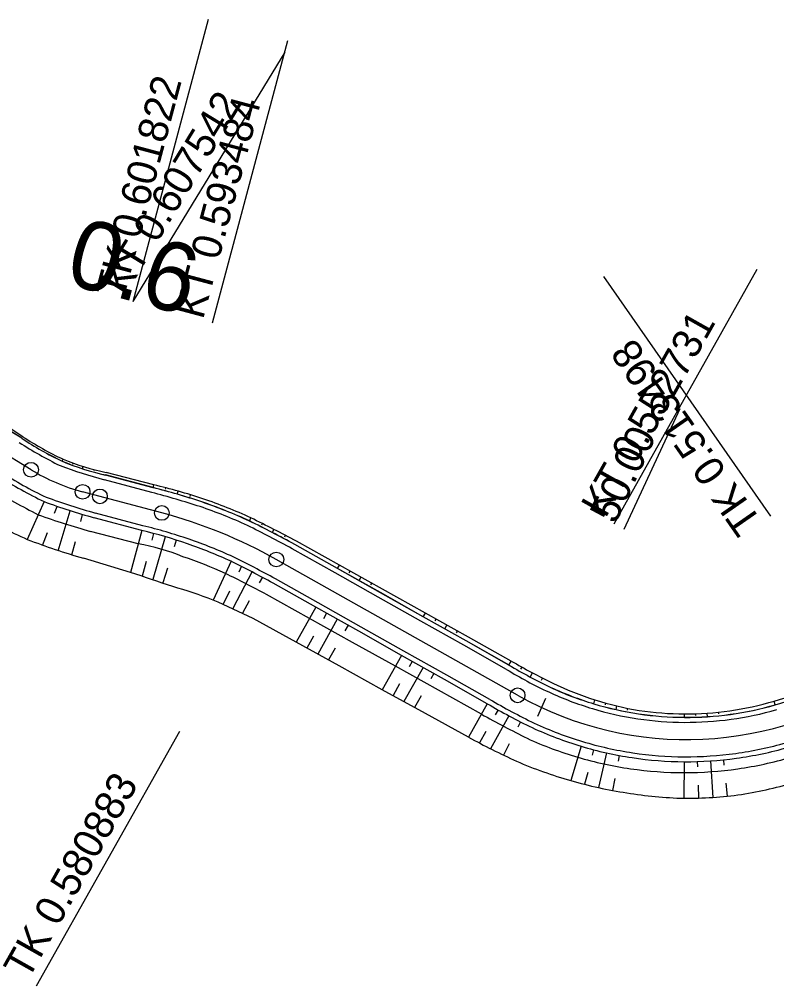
# Model space of a CAD drawing. Extents: x -481645 to -478728, y -1113199 to -1110710.
# Drawn here: x -479750.6 to -479673.5, y -1112836.4 to -1112738.2 of the extents above; entities that cross this region are included whole.
import ezdxf

# ---------------------------------------------------------------- set-up
doc = ezdxf.new("R2010")
doc.units = 0
for name, color, linetype in [('CP14_HRANA_TELESO', 7, 'Continuous'), ('CP14_OSA', 7, 'Continuous'), ('CP14_PRIKOP', 7, 'Continuous'), ('CP1_HATCH_SLOPE_L', 7, 'Continuous'), ('CP1_HATCH_SLOPE_R', 7, 'Continuous'), ('CP1_HLBODY', 7, 'Continuous'), ('CP1_HRANA_TELESO', 7, 'Continuous'), ('CP1_OSA', 7, 'Continuous'), ('CP1_STANICENI', 7, 'Continuous'), ('CP1_VOZOVKA', 7, 'Continuous'), ('CP1_ZPEVKRAJ', 7, 'Continuous')]:
    doc.layers.add(name, color=color, linetype=linetype)

msp = doc.modelspace()

# ---------------------------------------------------------------- linework, layer by layer
at = {"layer": 'CP14_HRANA_TELESO'}
for p, q in [((-479748.026, -1112787.238), (-479749.742, -1112791.086)), ((-479746.739, -1112787.764), (-479746.992, -1112788.444)), ((-479745.422, -1112788.209), (-479746.651, -1112792.264)), ((-479744.144, -1112788.563), (-479744.329, -1112789.258)), ((-479747.73, -1112790.424), (-479748.215, -1112791.723)), ((-479738.105, -1112790.173), (-479739.241, -1112794.437)), ((-479736.897, -1112790.494), (-479737.078, -1112791.172)), ((-479735.734, -1112790.814), (-479736.98, -1112795.144)), ((-479744.876, -1112791.312), (-479745.238, -1112792.669)), ((-479734.591, -1112791.158), (-479734.8, -1112791.822)), ((-479737.651, -1112793.328), (-479738.045, -1112794.804)), ((-479729.025, -1112793.302), (-479730.835, -1112797.248)), ((-479727.946, -1112793.813), (-479728.244, -1112794.423)), ((-479735.484, -1112793.994), (-479735.959, -1112795.501)), ((-479726.881, -1112794.351), (-479728.836, -1112798.106)), ((-479725.829, -1112794.916), (-479726.154, -1112795.505)), ((-479729.187, -1112796.348), (-479729.831, -1112797.664)), ((-479727.166, -1112797.334), (-479727.852, -1112798.574)), ((-479720.396, -1112797.971), (-479722.397, -1112801.528)), ((-479719.306, -1112798.584), (-479719.628, -1112799.156)), ((-479718.217, -1112799.197), (-479720.207, -1112802.735)), ((-479717.127, -1112799.81), (-479717.446, -1112800.376)), ((-479720.626, -1112800.929), (-479721.302, -1112802.131)), ((-479718.438, -1112802.14), (-479719.112, -1112803.338)), ((-479711.68, -1112802.875), (-479713.638, -1112806.354)), ((-479710.591, -1112803.488), (-479710.901, -1112804.039)), ((-479709.501, -1112804.1), (-479711.448, -1112807.56)), ((-479708.412, -1112804.713), (-479708.719, -1112805.259)), ((-479711.877, -1112805.774), (-479712.543, -1112806.957)), ((-479709.69, -1112806.984), (-479710.353, -1112808.163)), ((-479702.965, -1112807.778), (-479704.877, -1112811.178)), ((-479701.875, -1112808.391), (-479702.174, -1112808.921)), ((-479700.773, -1112809.01), (-479702.628, -1112812.36)), ((-479699.598, -1112809.634), (-479699.87, -1112810.17)), ((-479703.121, -1112810.605), (-479703.77, -1112811.759)), ((-479700.729, -1112811.86), (-479701.316, -1112813.015)), ((-479693.431, -1112812.103), (-479694.475, -1112815.584)), ((-479692.15, -1112812.463), (-479692.297, -1112813.023)), ((-479690.857, -1112812.777), (-479691.648, -1112816.311)), ((-479689.554, -1112813.044), (-479689.659, -1112813.606)), ((-479678.956, -1112813.485), (-479678.902, -1112814.024)), ((-479682.941, -1112813.675), (-479682.963, -1112817.393)), ((-479681.611, -1112813.659), (-479681.594, -1112814.208)), ((-479680.282, -1112813.595), (-479680.038, -1112817.304)), ((-479692.756, -1112814.778), (-479693.068, -1112815.972)), ((-479689.99, -1112815.383), (-479690.217, -1112816.598)), ((-479681.539, -1112816.066), (-479681.5, -1112817.375)), ((-479678.714, -1112815.873), (-479678.581, -1112817.182))]:
    msp.add_line(p, q, dxfattribs=at)
at = {"layer": 'CP14_OSA'}
msp.add_circle((-479742.357, -1112786.711), 0.75, dxfattribs=at)
at = {"layer": 'CP14_PRIKOP'}
for p, q in [((-479746.194, -1112783.128), (-479746.106, -1112782.931)), ((-479745.167, -1112783.548), (-479745.166, -1112783.544)), ((-479745.126, -1112783.437), (-479745.088, -1112783.335)), ((-479744.116, -1112783.903), (-479744.047, -1112783.674)), ((-479742.951, -1112784.089), (-479742.92, -1112783.973)), ((-479742.985, -1112784.215), (-479742.983, -1112784.21)), ((-479736.946, -1112785.824), (-479736.868, -1112785.532)), ((-479735.696, -1112785.99), (-479735.658, -1112785.844)), ((-479735.738, -1112786.146), (-479735.736, -1112786.142)), ((-479734.49, -1112786.489), (-479734.401, -1112786.18)), ((-479733.239, -1112786.866), (-479733.237, -1112786.862)), ((-479733.188, -1112786.704), (-479733.14, -1112786.55)), ((-479727.148, -1112789.212), (-479727.002, -1112788.893)), ((-479725.968, -1112789.771), (-479725.966, -1112789.766)), ((-479725.887, -1112789.606), (-479725.811, -1112789.45)), ((-479724.802, -1112790.36), (-479724.634, -1112790.038)), ((-479723.559, -1112790.812), (-479723.472, -1112790.655)), ((-479723.651, -1112790.978), (-479723.648, -1112790.974)), ((-479718.189, -1112794.049), (-479717.995, -1112793.705)), ((-479717.1, -1112794.662), (-479717.098, -1112794.658)), ((-479716.999, -1112794.484), (-479716.903, -1112794.313)), ((-479716.01, -1112795.275), (-479715.811, -1112794.921)), ((-479714.818, -1112795.704), (-479714.719, -1112795.53)), ((-479714.921, -1112795.888), (-479714.919, -1112795.884)), ((-479709.474, -1112798.953), (-479709.26, -1112798.572)), ((-479708.384, -1112799.566), (-479708.382, -1112799.562)), ((-479708.273, -1112799.368), (-479708.167, -1112799.18)), ((-479707.295, -1112800.179), (-479707.075, -1112799.789)), ((-479706.092, -1112800.59), (-479705.983, -1112800.397)), ((-479706.205, -1112800.791), (-479706.203, -1112800.787)), ((-479700.758, -1112803.856), (-479700.525, -1112803.441)), ((-479699.669, -1112804.469), (-479699.666, -1112804.464)), ((-479699.549, -1112804.256), (-479699.434, -1112804.052)), ((-479698.592, -1112805.074), (-479698.359, -1112804.654)), ((-479697.559, -1112805.622), (-479697.557, -1112805.618)), ((-479697.448, -1112805.402), (-479697.34, -1112805.192)), ((-479692.137, -1112807.793), (-479692.016, -1112807.39)), ((-479673.677, -1112807.901), (-479673.789, -1112807.511)), ((-479691.011, -1112808.109), (-479691.01, -1112808.104)), ((-479690.958, -1112807.908), (-479690.908, -1112807.717)), ((-479689.874, -1112808.385), (-479689.789, -1112808.005)), ((-479688.729, -1112808.62), (-479688.728, -1112808.615)), ((-479688.693, -1112808.432), (-479688.66, -1112808.253)), ((-479679.43, -1112808.818), (-479679.449, -1112808.637)), ((-479682.915, -1112809.175), (-479682.913, -1112808.821)), ((-479681.75, -1112808.976), (-479681.756, -1112808.801)), ((-479681.745, -1112809.161), (-479681.745, -1112809.156)), ((-479680.577, -1112809.105), (-479680.601, -1112808.74)), ((-479679.411, -1112809.008), (-479679.412, -1112809.003))]:
    msp.add_line(p, q, dxfattribs=at)
at = {"layer": 'CP1_HATCH_SLOPE_L'}
for p, q in [((-479689.036, -1112790.032), (-479683.354, -1112777.786)), ((-479697.033, -1112807.267), (-479697.875, -1112809.082))]:
    msp.add_line(p, q, dxfattribs=at)
at = {"layer": 'CP1_HATCH_SLOPE_R'}
for p, q in [((-479738.967, -1112766.916), (-479731.319, -1112738.218)), ((-479730.91, -1112769.063), (-479723.261, -1112740.365)), ((-479738.967, -1112766.916), (-479723.533, -1112741.541)), ((-479674.149, -1112788.733), (-479691.126, -1112764.364)), ((-479690.078, -1112789.499), (-479675.515, -1112763.614)), ((-479748.789, -1112836.441), (-479734.226, -1112810.556))]:
    msp.add_line(p, q, dxfattribs=at)
for centre in [(-479749.36, -1112784.004), (-479744.118, -1112786.242), (-479736.06, -1112788.389), (-479724.42, -1112793.126), (-479699.884, -1112806.929)]:
    msp.add_circle(centre, 0.75, dxfattribs=at)
at = {"layer": 'CP1_HLBODY'}
for p, q in [((-479737.075, -1112786.307), (-479741.906, -1112785.02)), ((-479737.976, -1112789.689), (-479742.807, -1112788.402)), ((-479718.434, -1112794.485), (-479722.792, -1112792.034)), ((-479714.077, -1112796.937), (-479718.434, -1112794.485)), ((-479720.15, -1112797.536), (-479724.508, -1112795.084)), ((-479715.793, -1112799.987), (-479720.15, -1112797.536)), ((-479709.719, -1112799.388), (-479714.077, -1112796.937)), ((-479705.361, -1112801.84), (-479709.719, -1112799.388)), ((-479711.435, -1112802.439), (-479715.793, -1112799.987)), ((-479707.077, -1112804.891), (-479711.435, -1112802.439)), ((-479701.003, -1112804.292), (-479705.361, -1112801.84)), ((-479702.72, -1112807.342), (-479707.077, -1112804.891))]:
    msp.add_line(p, q, dxfattribs=at)
for centre, radius, start, end in [((-479727.12, -1112744.728), 43.376, 237.30394, 243.61254), ((-479727.506, -1112732.198), 54.75, 249.81481, 254.75097), ((-479733.923, -1112756.778), 33.067, 236.09257, 245.14321), ((-479725.274, -1112725.552), 65.25, 249.783, 254.41239), ((-479768.127, -1112901.412), 119.219, 72.44127, 74.90236), ((-479748.936, -1112836.703), 51.75, 65.35523, 71.08481), ((-479751.971, -1112846.242), 58.258, 71.30256, 76.10014), ((-479796.531, -1112928.654), 155.25, 61.64255, 63.54041), ((-479748.936, -1112836.703), 48.25, 65.35523, 71.0848), ((-479793.34, -1112922.421), 144.75, 61.60669, 63.52819), ((-479679.72, -1112769.698), 40.617, 238.39935, 245.26178), ((-479682.723, -1112776.425), 33.25, 245.10929, 253.2944), ((-479667.107, -1112746.132), 70.816, 239.80832, 243.96374), ((-479682.723, -1112776.425), 33.25, 253.2944, 261.47951), ((-479682.723, -1112776.425), 33.25, 277.84973, 286.03484), ((-479682.723, -1112776.425), 33.25, 261.47951, 269.66462), ((-479682.723, -1112776.425), 33.25, 269.66462, 277.84973), ((-479682.723, -1112776.425), 36.75, 245.10929, 253.29441), ((-479682.723, -1112776.425), 36.75, 253.29441, 261.47952), ((-479682.723, -1112776.425), 36.75, 277.84974, 286.03485), ((-479682.723, -1112776.425), 36.75, 261.47952, 269.66463), ((-479682.723, -1112776.425), 36.75, 269.66463, 277.84974)]:
    msp.add_arc(centre, radius, start, end, dxfattribs=at)
at = {"layer": 'CP1_HRANA_TELESO'}
for p, q in [((-479750.196, -1112780.648), (-479754.388, -1112777.918)), ((-479736.868, -1112785.532), (-479741.71, -1112784.283)), ((-479717.995, -1112793.705), (-479722.363, -1112791.27)), ((-479739.241, -1112794.437), (-479744.033, -1112793.002)), ((-479713.627, -1112796.138), (-479717.995, -1112793.705)), ((-479709.26, -1112798.572), (-479713.627, -1112796.138)), ((-479704.891, -1112801.005), (-479709.26, -1112798.572)), ((-479722.397, -1112801.528), (-479726.776, -1112799.116)), ((-479718.017, -1112803.941), (-479722.397, -1112801.528)), ((-479700.525, -1112803.441), (-479704.891, -1112801.005)), ((-479713.638, -1112806.354), (-479718.017, -1112803.941)), ((-479709.258, -1112808.766), (-479713.638, -1112806.354)), ((-479704.877, -1112811.178), (-479709.258, -1112808.766))]:
    msp.add_line(p, q, dxfattribs=at)
for centre, radius, start, end in [((-479730.055, -1112749.379), 37.194, 237.21392, 244.43398), ((-479736.46, -1112759.38), 25.45, 247.72638, 258.09615), ((-479751.698, -1112846.967), 63.2, 71.73262, 76.42847), ((-479748.836, -1112836.742), 52.596, 65.47262, 71.20221), ((-479732.257, -1112752.325), 42.523, 237.87191, 245.72143), ((-479796.647, -1112930.496), 157.804, 61.91761, 63.81052), ((-479721.645, -1112716.835), 79.389, 249.27356, 253.6202), ((-480831.692, -1116047.821), 3431.903, 71.362892, 71.438514), ((-479746.515, -1112837.588), 43.28, 68.75975, 74.4995), ((-479783.243, -1112916.464), 130.227, 64.30363, 66.26951), ((-479671.82, -1112754.737), 56.534, 239.48605, 244.3372), ((-479682.309, -1112776.586), 32.297, 244.32239, 252.50828), ((-479682.838, -1112776.468), 32.335, 286.25143, 294.4366), ((-479682.291, -1112776.525), 32.361, 252.51191, 260.69779), ((-479682.91, -1112776.466), 32.357, 278.18798, 286.37323), ((-479682.693, -1112776.428), 32.394, 261.42663, 269.61174), ((-479682.901, -1112776.438), 32.384, 269.97969, 278.16493), ((-479672.549, -1112752.594), 66.911, 241.10848, 245.79557), ((-479683.533, -1112776.127), 40.945, 246.31349, 254.50042), ((-479682.89, -1112776.389), 40.871, 253.53302, 261.7182), ((-479683.498, -1112776.597), 40.909, 278.95829, 287.14494), ((-479681.964, -1112776.491), 40.914, 260.41448, 268.60101), ((-479682.736, -1112776.426), 40.967, 269.68236, 277.86748)]:
    msp.add_arc(centre, radius, start, end, dxfattribs=at)
at = {"layer": 'CP1_OSA'}
for p, q in [((-479749.36, -1112784.004), (-479797.961, -1112754.443)), ((-479736.06, -1112788.389), (-479744.118, -1112786.242)), ((-479699.884, -1112806.929), (-479724.42, -1112793.126))]:
    msp.add_line(p, q, dxfattribs=at)
for centre, radius, start, end in [((-479738.967, -1112766.916), 20, 238.69061, 255.07697), ((-479748.936, -1112836.703), 50, 60.63784, 75.07701), ((-479682.723, -1112776.425), 35, 240.63783, 304.86326)]:
    msp.add_arc(centre, radius, start, end, dxfattribs=at)
at = {"layer": 'CP1_STANICENI'}
for p, q in [((-479737.075, -1112786.307), (-479741.906, -1112785.02)), ((-479737.976, -1112789.689), (-479742.807, -1112788.402)), ((-479718.434, -1112794.485), (-479722.792, -1112792.034)), ((-479714.077, -1112796.937), (-479718.434, -1112794.485)), ((-479720.15, -1112797.536), (-479724.508, -1112795.084)), ((-479715.793, -1112799.987), (-479720.15, -1112797.536)), ((-479709.719, -1112799.388), (-479714.077, -1112796.937)), ((-479705.361, -1112801.84), (-479709.719, -1112799.388)), ((-479711.435, -1112802.439), (-479715.793, -1112799.987)), ((-479707.077, -1112804.891), (-479711.435, -1112802.439)), ((-479701.003, -1112804.292), (-479705.361, -1112801.84)), ((-479702.72, -1112807.342), (-479707.077, -1112804.891))]:
    msp.add_line(p, q, dxfattribs=at)
for centre, radius, start, end in [((-479727.12, -1112744.728), 43.376, 237.30394, 243.61254), ((-479727.506, -1112732.198), 54.75, 249.81481, 254.75097), ((-479733.923, -1112756.778), 33.067, 236.09257, 245.14321), ((-479725.274, -1112725.552), 65.25, 249.783, 254.41239), ((-479768.127, -1112901.412), 119.219, 72.44127, 74.90236), ((-479748.936, -1112836.703), 51.75, 65.35523, 71.08481), ((-479751.971, -1112846.242), 58.258, 71.30256, 76.10014), ((-479796.531, -1112928.654), 155.25, 61.64255, 63.54041), ((-479748.936, -1112836.703), 48.25, 65.35523, 71.0848), ((-479793.34, -1112922.421), 144.75, 61.60669, 63.52819), ((-479679.72, -1112769.698), 40.617, 238.39935, 245.26178), ((-479682.723, -1112776.425), 33.25, 245.10929, 253.2944), ((-479667.107, -1112746.132), 70.816, 239.80832, 243.96374), ((-479682.723, -1112776.425), 33.25, 253.2944, 261.47951), ((-479682.723, -1112776.425), 33.25, 277.84973, 286.03484), ((-479682.723, -1112776.425), 33.25, 261.47951, 269.66462), ((-479682.723, -1112776.425), 33.25, 269.66462, 277.84973), ((-479682.723, -1112776.425), 36.75, 245.10929, 253.29441), ((-479682.723, -1112776.425), 36.75, 253.29441, 261.47952), ((-479682.723, -1112776.425), 36.75, 277.84974, 286.03485), ((-479682.723, -1112776.425), 36.75, 261.47952, 269.66463), ((-479682.723, -1112776.425), 36.75, 269.66463, 277.84974)]:
    msp.add_arc(centre, radius, start, end, dxfattribs=at)
at = {"layer": 'CP1_VOZOVKA'}
for p, q in [((-479750.291, -1112780.804), (-479754.563, -1112778.206)), ((-479736.946, -1112785.824), (-479741.777, -1112784.537)), ((-479738.105, -1112790.173), (-479742.936, -1112788.885)), ((-479718.189, -1112794.049), (-479722.547, -1112791.598)), ((-479713.831, -1112796.501), (-479718.189, -1112794.049)), ((-479720.396, -1112797.971), (-479724.753, -1112795.52)), ((-479709.474, -1112798.953), (-479713.831, -1112796.501)), ((-479716.038, -1112800.423), (-479720.396, -1112797.971)), ((-479705.116, -1112801.404), (-479709.474, -1112798.953)), ((-479711.68, -1112802.875), (-479716.038, -1112800.423)), ((-479700.758, -1112803.856), (-479705.116, -1112801.404)), ((-479707.322, -1112805.326), (-479711.68, -1112802.875)), ((-479702.965, -1112807.778), (-479707.322, -1112805.326))]:
    msp.add_line(p, q, dxfattribs=at)
for centre, radius, start, end in [((-479732.679, -1112754.532), 31.629, 236.16285, 244.7031), ((-479736.491, -1112760.331), 24.776, 246.94457, 257.68136), ((-479731.246, -1112752.025), 39.007, 236.75667, 244.52035), ((-479752.169, -1112846.943), 62.986, 71.32236, 76.01329), ((-479724.953, -1112724.603), 66.75, 249.77765, 254.3711), ((-479748.936, -1112836.703), 52.25, 65.35523, 71.08481), ((-479796.987, -1112929.544), 156.75, 61.64733, 63.54207), ((-479749.298, -1112837.095), 48.239, 70.8291, 76.58253), ((-479748.936, -1112836.703), 47.75, 65.35522, 71.0848), ((-479792.884, -1112921.531), 143.25, 61.60119, 63.52635), ((-479671.577, -1112754.49), 57.346, 239.4121, 244.23215), ((-479682.723, -1112776.425), 32.75, 245.10929, 253.2944), ((-479682.723, -1112776.425), 32.75, 286.03484, 294.21995), ((-479671.627, -1112754.595), 61.729, 239.49162, 244.29533), ((-479682.723, -1112776.425), 32.75, 253.2944, 261.47951), ((-479682.723, -1112776.425), 32.75, 277.84973, 286.03484), ((-479682.723, -1112776.425), 32.75, 261.47951, 269.66462), ((-479682.723, -1112776.425), 32.75, 269.66462, 277.84973), ((-479682.723, -1112776.425), 37.25, 245.1093, 253.29441), ((-479682.723, -1112776.425), 37.25, 253.29441, 261.47952), ((-479682.723, -1112776.425), 37.25, 277.84974, 286.03485), ((-479682.723, -1112776.425), 37.25, 261.47952, 269.66463), ((-479682.723, -1112776.425), 37.25, 269.66463, 277.84974)]:
    msp.add_arc(centre, radius, start, end, dxfattribs=at)
at = {"layer": 'CP1_ZPEVKRAJ'}
for p, q in [((-479750.286, -1112780.796), (-479754.558, -1112778.197)), ((-479736.943, -1112785.815), (-479741.775, -1112784.527)), ((-479738.468, -1112791.535), (-479743.305, -1112790.27)), ((-479718.184, -1112794.041), (-479722.542, -1112791.589)), ((-479713.826, -1112796.492), (-479718.184, -1112794.041)), ((-479721.041, -1112799.119), (-479725.41, -1112796.688)), ((-479709.469, -1112798.944), (-479713.826, -1112796.492)), ((-479716.672, -1112801.55), (-479721.041, -1112799.119)), ((-479705.111, -1112801.396), (-479709.469, -1112798.944)), ((-479712.303, -1112803.982), (-479716.672, -1112801.55)), ((-479700.753, -1112803.847), (-479705.111, -1112801.396)), ((-479707.934, -1112806.413), (-479712.303, -1112803.982)), ((-479703.565, -1112808.844), (-479707.934, -1112806.413))]:
    msp.add_line(p, q, dxfattribs=at)
for centre, radius, start, end in [((-479734.274, -1112757.344), 28.396, 235.67649, 245.18844), ((-479737.125, -1112762.319), 22.689, 246.45181, 258.17534), ((-479720.135, -1112731.681), 63.621, 238.47733, 243.40256), ((-479756.31, -1112861.074), 77.712, 71.76664, 75.56885), ((-479748.936, -1112836.703), 52.26, 65.35523, 71.08481), ((-479724.296, -1112721.737), 71.12, 250.00099, 254.49743), ((-479796.996, -1112929.562), 156.78, 61.64742, 63.5421), ((-479742.544, -1112814.356), 23.182, 68.12573, 79.87363), ((-479748.72, -1112836.789), 46.375, 65.64291, 71.37256), ((-479791.022, -1112919.409), 139.16, 61.86914, 63.80503), ((-479676.036, -1112762.814), 47.903, 238.93695, 244.70696), ((-479682.723, -1112776.425), 32.74, 245.10929, 253.2944), ((-479682.723, -1112776.425), 32.74, 286.03484, 294.21995), ((-479682.723, -1112776.425), 32.74, 253.2944, 261.47951), ((-479682.723, -1112776.425), 32.74, 277.84973, 286.03484), ((-479645.849, -1112704.915), 118.88, 240.95487, 243.49397), ((-479682.723, -1112776.425), 32.74, 261.47951, 269.66462), ((-479682.723, -1112776.425), 32.74, 269.66462, 277.84973), ((-479682.914, -1112776.354), 38.43, 245.41248, 253.59771), ((-479682.922, -1112776.381), 38.401, 253.59783, 261.78305), ((-479682.922, -1112776.468), 38.314, 278.15385, 286.33908), ((-479682.926, -1112776.41), 38.372, 261.78337, 269.96859), ((-479682.926, -1112776.439), 38.343, 269.96831, 278.15353)]:
    msp.add_arc(centre, radius, start, end, dxfattribs=at)

# ---------------------------------------------------------------- texts
at = {"layer": 'CP14_OSA'}
msp.add_text('0.6', height=7, rotation=345.03137, dxfattribs=at).set_placement((-479746.1, -1112765.008))
at = {"layer": 'CP1_HATCH_SLOPE_L'}
msp.add_text('50.00', height=3, rotation=65.10929, dxfattribs=at).set_placement((-479689.944, -1112789.612))
at = {"layer": 'CP1_HATCH_SLOPE_R'}
for s, height, rotation, p in [('TK 0.601822', 3, 75.077, (-479739.934, -1112766.659)), ('KT 0.607542', 3, 58.69064, (-479739.822, -1112766.397)), ('KT 0.593484', 3, 75.077, (-479731.876, -1112768.807)), ('KT 0.552731', 2.999, 60.63783, (-479690.95, -1112789.009)), ('TK 0.513498', 3, 124.86326, (-479674.969, -1112789.306)), ('TK 0.580883', 2.999, 60.63783, (-479749.661, -1112835.951))]:
    msp.add_text(s, height=height, rotation=rotation, dxfattribs=at).set_placement(p)

doc.saveas('drawing.dxf')
